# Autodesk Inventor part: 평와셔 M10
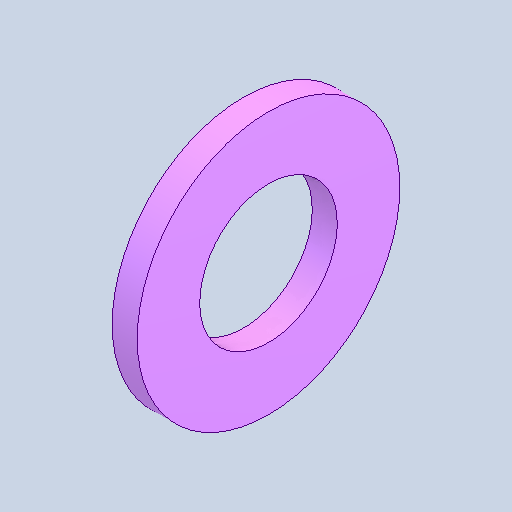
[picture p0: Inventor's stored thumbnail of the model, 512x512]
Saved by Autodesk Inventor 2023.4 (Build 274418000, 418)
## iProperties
Created: 2024-09
Part Number: 평와셔 M10
Material: 강철, 연강
Description: 평면 와셔
Document SubType Name: Modeling
Designer: EDU
Density: 7.85 g/cm^3
Appearance: 기본값
Author: jhkim
Sending System: Autodesk Inventor 2025
Preprocessor: ST-DEVELOPER v20
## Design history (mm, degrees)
feature "Solid1"
node "솔리드1"
